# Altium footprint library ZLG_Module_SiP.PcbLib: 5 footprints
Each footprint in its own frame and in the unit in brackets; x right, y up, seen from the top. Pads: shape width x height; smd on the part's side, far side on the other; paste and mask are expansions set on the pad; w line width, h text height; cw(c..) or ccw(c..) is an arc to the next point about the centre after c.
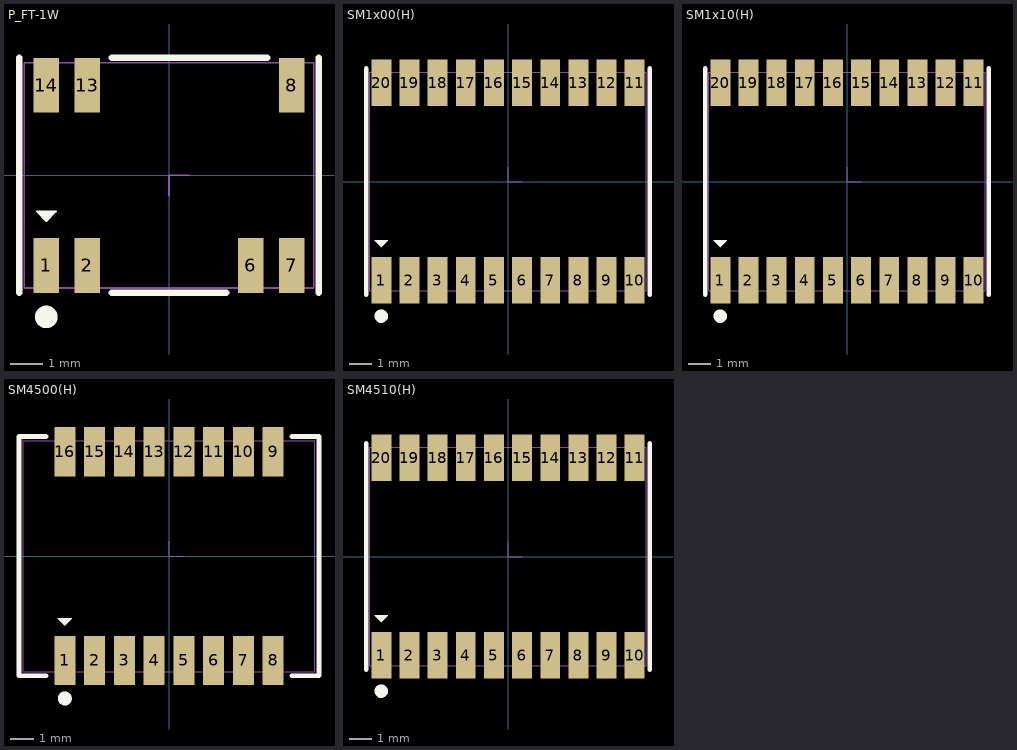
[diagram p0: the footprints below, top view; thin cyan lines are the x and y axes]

## P_FT-1W [mm] "20230306新修订"
height 3
pads (7):
  rect 0.8x1.7 smd: 1(-3.81,-2.8) 2(-2.54,-2.8) 6(2.54,-2.8) 7(3.81,-2.8) 8(3.81,2.8) 13(-2.54,2.8) 14(-3.81,2.8)
Top Overlay:
  circle w0.5: c-3.81,-4.4 r0.1
  region: -4.11,-1.125 -3.81,-1.425 -3.51,-1.125
  region: -4.11,-1.125 -3.81,-1.425 -3.51,-1.125
  lines w0.05: -4.11,-1.125 -3.81,-1.425 ; -4.11,-1.125 -3.51,-1.125 ; -4.11,-1.125 -3.51,-1.125 ; -4.11,-1.125 -3.81,-1.425 ; -3.81,-1.425 -3.51,-1.125 ; -3.81,-1.425 -3.51,-1.125
  lines w0.2: -4.65,-3.65 -4.65,3.65 ; -1.778,-3.65 1.778,-3.65 ; -1.778,3.65 3.048,3.65 ; 4.65,-3.65 4.65,3.65
Mechanical 13:
  lines w0.05: -4.5,-3.5 -4.5,3.5 4.5,3.5 4.5,-3.5 -4.5,-3.5
Mechanical 15:
  lines w0.05: 0,-0.635 0,0 0.635,0
3D body "3d-2.stp": height 3.01, standoff -0.01, extent -4.5,-3.5 4.5,3.5

## SM1x00(H) [mm]
height 3
pads (20):
  rect 0.9x2.1 smd: 1(-5.715,-4.45) 2(-4.445,-4.45) 3(-3.175,-4.45) 4(-1.905,-4.45) 5(-0.635,-4.45) 6(0.635,-4.45) 7(1.905,-4.45) 8(3.175,-4.45) 9(4.445,-4.45) 10(5.715,-4.45) 11(5.715,4.45) 12(4.445,4.45) 13(3.175,4.45) 14(1.905,4.45) 15(0.635,4.45) 16(-0.635,4.45) 17(-1.905,4.45) 18(-3.175,4.45) 19(-4.445,4.45) 20(-5.715,4.45)
Top Overlay:
  circle w0.4: c-5.715,-6.074 r0.1
  region: -6.015,-2.65 -5.715,-2.95 -5.415,-2.65
  lines w0.05: -6.015,-2.65 -5.715,-2.95 -5.415,-2.65 -6.015,-2.65
  lines w0.2: -6.4,-5.1 -6.4,5.1 ; 6.4,-5.1 6.4,5.1
Mechanical 13:
  lines w0.05: -6.225,-4.925 -6.225,4.925 6.225,4.925 6.225,-4.925 -6.225,-4.925
Mechanical 15:
  lines w0.05: 0,0.635 0,0 0.635,0

## SM1x10(H) [mm]
height 3
pads (20):
  rect 0.9x2.1 smd: 1(-5.715,-4.45) 2(-4.445,-4.45) 3(-3.175,-4.45) 4(-1.905,-4.45) 5(-0.635,-4.45) 6(0.635,-4.45) 7(1.905,-4.45) 8(3.175,-4.45) 9(4.445,-4.45) 10(5.715,-4.45) 11(5.715,4.45) 12(4.445,4.45) 13(3.175,4.45) 14(1.905,4.45) 15(0.635,4.45) 16(-0.635,4.45) 17(-1.905,4.45) 18(-3.175,4.45) 19(-4.445,4.45) 20(-5.715,4.45)
Top Overlay:
  circle w0.4: c-5.715,-6.074 r0.1
  region: -6.015,-2.65 -5.715,-2.95 -5.415,-2.65
  lines w0.05: -6.015,-2.65 -5.415,-2.65 -5.715,-2.95 -6.015,-2.65
  lines w0.2: -6.4,-5.1 -6.4,5.1 ; 6.4,-5.1 6.4,5.1
Mechanical 13:
  lines w0.05: -6.225,-4.925 6.225,-4.925 6.225,4.925 -6.225,4.925 -6.225,-4.925
Mechanical 15:
  lines w0.05: 0,0.635 0,0 0.635,0

## SM4500(H) [mm]
height 3
pads (16):
  rect 0.9x2.1 smd: 1(-4.445,-4.45) 2(-3.175,-4.45) 3(-1.905,-4.45) 4(-0.635,-4.45) 5(0.635,-4.45) 6(1.905,-4.45) 7(3.175,-4.45) 8(4.445,-4.45) 9(4.445,4.45) 10(3.175,4.45) 11(1.905,4.45) 12(0.635,4.45) 13(-0.635,4.45) 14(-1.905,4.45) 15(-3.175,4.45) 16(-4.445,4.45)
Top Overlay:
  circle w0.4: c-4.445,-6.074 r0.1
  region: -4.745,-2.65 -4.445,-2.95 -4.145,-2.65
  lines w0.05: -4.745,-2.65 -4.445,-2.95 -4.145,-2.65 -4.745,-2.65
  lines w0.2: -5.232,-5.1 -6.4,-5.1 -6.4,5.1 -5.232,5.1 ; 5.232,-5.1 6.4,-5.1 6.4,5.1 5.232,5.1
Mechanical 13:
  lines w0.05: -6.225,-4.925 6.225,-4.925 6.225,4.925 -6.225,4.925 -6.225,-4.925
Mechanical 15:
  lines w0.05: 0,0.635 0,0 0.635,0

## SM4510(H) [mm]
height 3
pads (20):
  rect 0.9x2.1 smd: 1(-5.715,-4.45) 2(-4.445,-4.45) 3(-3.175,-4.45) 4(-1.905,-4.45) 5(-0.635,-4.45) 6(0.635,-4.45) 7(1.905,-4.45) 8(3.175,-4.45) 9(4.445,-4.45) 10(5.715,-4.45) 11(5.715,4.45) 12(4.445,4.45) 13(3.175,4.45) 14(1.905,4.45) 15(0.635,4.45) 16(-0.635,4.45) 17(-1.905,4.45) 18(-3.175,4.45) 19(-4.445,4.45) 20(-5.715,4.45)
Top Overlay:
  circle w0.4: c-5.715,-6.074 r0.1
  region: -6.015,-2.65 -5.715,-2.95 -5.415,-2.65
  lines w0.05: -6.015,-2.65 -5.715,-2.95 -5.415,-2.65 -6.015,-2.65
  lines w0.2: -6.4,-5.1 -6.4,5.1 ; 6.4,-5.1 6.4,5.1
Mechanical 13:
  lines w0.05: -6.225,-4.925 -6.225,4.925 6.225,4.925 6.225,-4.925 -6.225,-4.925
Mechanical 15:
  lines w0.05: 0,0.635 0,0 0.635,0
